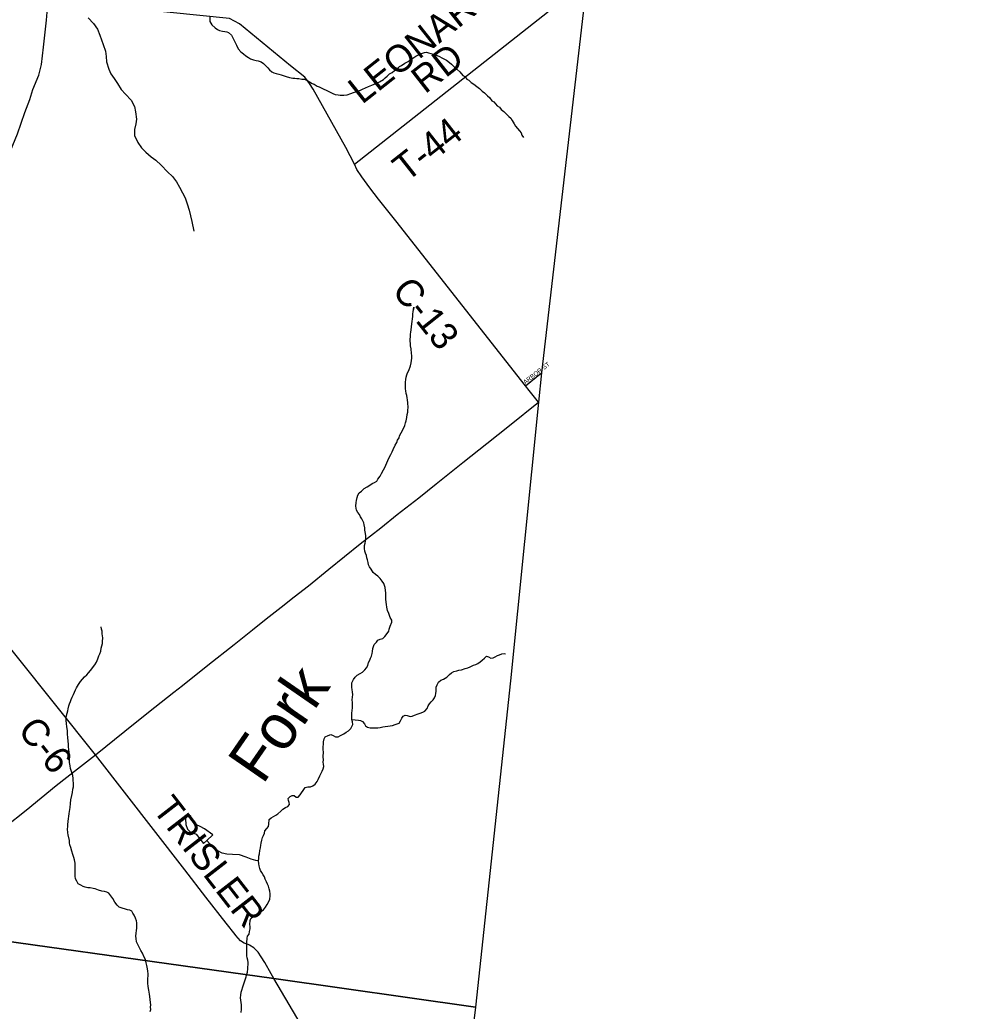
# Model space of a CAD drawing. Extents: x 1310247 to 1664935, y 235267 to 584339.
# Drawn here: x 1525713 to 1536205, y 325986 to 336990 of the extents above; entities that cross this region are included whole.
import ezdxf

# ---------------------------------------------------------------- set-up
doc = ezdxf.new("R2010")
doc.units = 0
for name, color, linetype in [('GM_X_Adjacent_County', 7, 'Continuous'), ('GM_X_County', 7, 'Continuous'), ('GM_X_County_Road', 7, 'Continuous'), ('GM_X_County_Road_Text', 7, 'Continuous'), ('GM_X_Minor_Lake', 7, 'Continuous'), ('GM_X_Minor_River', 7, 'Continuous'), ('GM_X_Minor_River_Text', 7, 'Continuous'), ('GM_X_State_Route', 7, 'Continuous'), ('GM_X_Township', 7, 'Continuous'), ('GM_X_Township_Road', 7, 'Continuous'), ('GM_X_Township_Road_Text', 7, 'Continuous'), ('GM_X_Township_Subdivision', 7, 'Continuous'), ('GM_X_Township_Subdivision_Text', 7, 'Continuous')]:
    doc.layers.add(name, color=color, linetype=linetype)

msp = doc.modelspace()

# ---------------------------------------------------------------- linework, layer by layer
at = {"layer": 'GM_X_Adjacent_County'}
msp.add_lwpolyline([(1536205, 372785), (1535397, 366216), (1534972, 363186), (1534842, 361983), (1534628, 360199), (1533821, 353172), (1533276, 348457), (1532824, 344490), (1532312, 340083), (1532006, 337422), (1531505, 333071), (1531469, 332747), (1531158, 329654), (1530772, 326029), (1530509, 323916), (1530186, 322432), (1530006, 319686), (1529806, 317987)], dxfattribs=at)
at = {"layer": 'GM_X_County'}
msp.add_lwpolyline([(1536205, 372785), (1535397, 366216), (1534972, 363186), (1534842, 361983), (1534628, 360199), (1533821, 353172), (1533276, 348457), (1532824, 344490), (1532312, 340083), (1532006, 337422), (1531505, 333071), (1531469, 332747), (1531158, 329654), (1530772, 326029), (1530509, 323916), (1530186, 322432), (1530006, 319686), (1529806, 317987)], dxfattribs=at)
at = {"layer": 'GM_X_County_Road'}
for points in [[(1526553, 328831), (1524772, 331056), (1524725, 331125), (1524709, 331149), (1524687, 331191), (1524676, 331227), (1524669, 331304), (1524684, 331466), (1524975, 333549), (1525003, 333751), (1525037, 334030), (1525046, 334096), (1525054, 334172), (1525089, 334279), (1525138, 334396), (1525688, 335724), (1525769, 335962), (1525824, 336105), (1525859, 336217), (1525923, 336377), (1525954, 336496), (1525977, 336688), (1526010, 336987), (1526027, 337210)], [(1531469, 332747), (1531366, 332875), (1531324, 332929), (1529885, 334759), (1529693, 334999), (1529599, 335124), (1529508, 335247), (1529454, 335330), (1529429, 335389), (1529333, 335574), (1528970, 336221), (1528927, 336285), (1528876, 336353), (1528719, 336480), (1528150, 336944), (1528040, 337005), (1526027, 337210)]]:
    msp.add_lwpolyline(points, dxfattribs=at)
at = {"layer": 'GM_X_Minor_Lake'}
for points in [[(1527788, 327882), (1527855, 327943), (1527764, 328011), (1527716, 328036), (1527676, 328053), (1527649, 328077), (1527623, 328118), (1527610, 328148), (1527586, 328169), (1527558, 328163), (1527553, 328121), (1527554, 328059), (1527573, 328006), (1527611, 327971), (1527643, 327961), (1527671, 327950)], [(1527671, 327950), (1527751, 327846), (1527788, 327882)]]:
    msp.add_lwpolyline(points, dxfattribs=at)
at = {"layer": 'GM_X_Minor_River'}
for points in [[(1526470, 337013), (1526531, 336948), (1526574, 336887), (1526601, 336820), (1526620, 336767), (1526637, 336715), (1526664, 336642), (1526671, 336584), (1526676, 336523), (1526703, 336441), (1526724, 336390), (1526759, 336339), (1526798, 336282), (1526838, 336218), (1526887, 336165), (1526950, 336099), (1526985, 336028), (1526998, 335968), (1527007, 335889), (1527000, 335837), (1526987, 335773), (1526985, 335707), (1527022, 335628), (1527063, 335571), (1527111, 335520), (1527170, 335471), (1527222, 335432), (1527281, 335377), (1527352, 335303), (1527409, 335250), (1527452, 335193), (1527487, 335132), (1527519, 335070), (1527550, 335013), (1527571, 334948), (1527592, 334876), (1527609, 334815), (1527624, 334751), (1527646, 334646)], [(1527823, 337024), (1527822, 336970), (1527845, 336934), (1527880, 336903), (1527906, 336884), (1527930, 336872), (1527964, 336863), (1527988, 336860), (1528010, 336856), (1528031, 336850), (1528061, 336819), (1528072, 336797), (1528090, 336768), (1528099, 336746), (1528117, 336707), (1528138, 336667), (1528167, 336634), (1528197, 336611), (1528222, 336591), (1528250, 336572), (1528275, 336556), (1528305, 336547), (1528337, 336538), (1528359, 336534), (1528391, 336523), (1528416, 336507), (1528467, 336457), (1528485, 336435), (1528511, 336412), (1528532, 336402), (1528558, 336395), (1528588, 336387), (1528614, 336380), (1528646, 336367), (1528670, 336361), (1528707, 336350), (1528743, 336343), (1528765, 336343), (1528787, 336338), (1528809, 336338), (1528845, 336333), (1528869, 336331), (1528905, 336316), (1528928, 336301), (1528958, 336285), (1528980, 336276), (1529014, 336255), (1529035, 336247), (1529079, 336224), (1529119, 336205), (1529156, 336186), (1529188, 336172), (1529214, 336163), (1529248, 336156), (1529270, 336154), (1529308, 336153), (1529348, 336158), (1529386, 336171), (1529418, 336183)], [(1529418, 336183), (1529455, 336194), (1529495, 336211), (1529517, 336221), (1529549, 336234), (1529582, 336250), (1529620, 336265), (1529665, 336282), (1529705, 336301), (1529750, 336326), (1529768, 336348), (1529790, 336366), (1529815, 336389), (1529845, 336405), (1529870, 336426), (1529902, 336447), (1529929, 336473), (1529951, 336483), (1529986, 336508), (1530022, 336529), (1530052, 336549), (1530075, 336566), (1530107, 336586), (1530129, 336597), (1530154, 336611), (1530182, 336620), (1530206, 336628), (1530228, 336631), (1530296, 336610), (1530318, 336603), (1530344, 336593), (1530371, 336582), (1530397, 336570), (1530421, 336557), (1530447, 336542), (1530482, 336516), (1530506, 336497), (1530539, 336466), (1530563, 336444), (1530598, 336413), (1530631, 336372), (1530653, 336360), (1530676, 336333), (1530698, 336321), (1530722, 336296), (1530753, 336275), (1530785, 336249), (1530816, 336226), (1530844, 336199), (1530871, 336181), (1530903, 336148), (1530926, 336129), (1530953, 336091), (1530975, 336078), (1531012, 336035), (1531038, 336019), (1531057, 335996), (1531087, 335972), (1531110, 335945), (1531140, 335918), (1531163, 335898), (1531177, 335871), (1531198, 335837), (1531216, 335808), (1531237, 335782), (1531259, 335759), (1531276, 335735), (1531286, 335711), (1531303, 335684)], [(1530075, 333726), (1530079, 333750), (1530082, 333776), (1530087, 333802), (1530084, 333776)], [(1529636, 330857), (1529611, 330892), (1529594, 330918), (1529584, 330940), (1529579, 330968), (1529573, 330995), (1529566, 331019), (1529560, 331043), (1529551, 331069), (1529541, 331094), (1529540, 331122), (1529540, 331154), (1529545, 331180), (1529549, 331204), (1529552, 331228), (1529553, 331264), (1529549, 331290), (1529544, 331324), (1529541, 331350), (1529535, 331383), (1529530, 331405), (1529520, 331429), (1529509, 331451), (1529495, 331474), (1529482, 331500), (1529464, 331522), (1529449, 331547), (1529445, 331571), (1529444, 331593), (1529446, 331631), (1529451, 331653), (1529458, 331689), (1529466, 331713), (1529479, 331739), (1529505, 331760), (1529536, 331788), (1529570, 331805), (1529599, 331825), (1529623, 331842), (1529651, 331856), (1529674, 331871), (1529688, 331893), (1529711, 331923), (1529729, 331956), (1529750, 331994), (1529765, 332022), (1529797, 332099), (1529809, 332125), (1529830, 332165), (1529845, 332195), (1529857, 332220), (1529880, 332270), (1529897, 332300), (1529905, 332324), (1529922, 332349), (1529928, 332371), (1529947, 332405), (1529964, 332439), (1529985, 332486), (1529995, 332516), (1530002, 332540), (1530009, 332576), (1530013, 332608), (1530020, 332634), (1530020, 332656), (1530023, 332688), (1530020, 332740), (1530017, 332771), (1530013, 332793), (1530008, 332819), (1530002, 332843), (1529999, 332873), (1529995, 332895), (1529994, 332918), (1529995, 332970), (1529998, 332996), (1530002, 333022), (1530009, 333048), (1530017, 333071), (1530030, 333099), (1530051, 333151), (1530055, 333181), (1530060, 333207), (1530065, 333235), (1530065, 333263), (1530062, 333287), (1530055, 333339), (1530051, 333370), (1530050, 333398), (1530047, 333424), (1530047, 333446), (1530050, 333470), (1530050, 333500), (1530053, 333522), (1530055, 333548), (1530060, 333582), (1530065, 333614), (1530067, 333642), (1530070, 333670), (1530074, 333698), (1530075, 333726)], [(1528824, 328387), (1528840, 328410), (1528857, 328436), (1528881, 328468), (1528908, 328475), (1528940, 328478), (1528966, 328486), (1528992, 328505), (1529013, 328537), (1529023, 328559), (1529042, 328597), (1529059, 328628), (1529069, 328650), (1529080, 328676), (1529089, 328702), (1529083, 328728), (1529080, 328750), (1529082, 328778), (1529081, 328810), (1529082, 328865), (1529080, 328887), (1529079, 328919), (1529082, 328951), (1529082, 328975), (1529091, 329009), (1529101, 329031), (1529136, 329048), (1529166, 329057), (1529192, 329047), (1529218, 329030), (1529246, 329032), (1529272, 329045), (1529310, 329066), (1529337, 329082), (1529361, 329097), (1529388, 329123), (1529400, 329147), (1529411, 329169), (1529405, 329197), (1529400, 329223), (1529398, 329245), (1529397, 329269), (1529397, 329291), (1529402, 329329), (1529406, 329351), (1529407, 329389), (1529404, 329414), (1529402, 329442), (1529407, 329472), (1529410, 329500), (1529406, 329526), (1529401, 329556), (1529399, 329580), (1529400, 329630), (1529417, 329666), (1529434, 329694), (1529456, 329715), (1529491, 329735), (1529517, 329750), (1529541, 329776), (1529560, 329797), (1529574, 329823), (1529585, 329857), (1529598, 329883), (1529606, 329905), (1529617, 329927), (1529625, 329957), (1529628, 329979), (1529632, 330011), (1529639, 330034), (1529647, 330058), (1529672, 330084), (1529688, 330106), (1529713, 330115), (1529741, 330123), (1529763, 330146), (1529790, 330180), (1529807, 330203), (1529811, 330227), (1529824, 330259), (1529843, 330303), (1529843, 330325), (1529824, 330356), (1529816, 330380), (1529807, 330402), (1529795, 330434), (1529788, 330469), (1529783, 330499), (1529779, 330527), (1529774, 330559), (1529775, 330607), (1529774, 330629), (1529770, 330654), (1529767, 330688), (1529761, 330710), (1529754, 330734), (1529734, 330761), (1529713, 330789), (1529687, 330814), (1529662, 330834), (1529636, 330857)], [(1526252, 328948), (1526246, 329024), (1526244, 329061), (1526241, 329101), (1526236, 329143), (1526233, 329181), (1526229, 329211), (1526228, 329241), (1526233, 329269), (1526246, 329319), (1526250, 329341), (1526257, 329377), (1526265, 329399), (1526274, 329425), (1526282, 329447), (1526295, 329473), (1526308, 329502), (1526320, 329528), (1526333, 329552), (1526343, 329574), (1526364, 329612), (1526387, 329645), (1526409, 329673), (1526430, 329697), (1526456, 329720), (1526477, 329742), (1526499, 329767), (1526545, 329832), (1526563, 329862), (1526578, 329896), (1526591, 329932), (1526601, 329954), (1526614, 329984), (1526617, 330014), (1526625, 330041), (1526630, 330069), (1526632, 330091), (1526633, 330130), (1526632, 330154), (1526628, 330176), (1526627, 330206), (1526621, 330228), (1526616, 330252)], [(1529400, 329223), (1529472, 329216), (1529494, 329211), (1529517, 329201), (1529537, 329176), (1529550, 329154), (1529572, 329139), (1529600, 329133), (1529658, 329131), (1529686, 329133), (1529714, 329136), (1529742, 329142), (1529768, 329145), (1529796, 329151), (1529825, 329154), (1529851, 329159), (1529879, 329169), (1529901, 329174), (1529923, 329184), (1529940, 329208), (1529952, 329238), (1529969, 329261), (1529991, 329271), (1530013, 329270), (1530047, 329258), (1530069, 329259), (1530095, 329271), (1530136, 329288), (1530158, 329293), (1530188, 329305), (1530210, 329316), (1530233, 329346), (1530247, 329374), (1530262, 329396), (1530280, 329421), (1530301, 329443), (1530317, 329465), (1530326, 329489), (1530330, 329511), (1530335, 329537), (1530336, 329581), (1530344, 329607), (1530361, 329638), (1530386, 329660), (1530414, 329673), (1530452, 329695), (1530481, 329722), (1530503, 329742), (1530532, 329755), (1530562, 329764), (1530584, 329772), (1530614, 329775), (1530656, 329789), (1530685, 329798), (1530713, 329809), (1530749, 329827), (1530776, 329836), (1530798, 329846), (1530822, 329863), (1530846, 329881), (1530871, 329906), (1530893, 329926), (1530915, 329920), (1530941, 329905), (1530967, 329908), (1530989, 329918), (1531014, 329934), (1531038, 329941), (1531062, 329953), (1531088, 329956), (1531103, 329953)], [(1527152, 326175), (1527145, 326219), (1527138, 326260), (1527135, 326298), (1527133, 326320), (1527134, 326348), (1527136, 326380), (1527137, 326402), (1527135, 326430), (1527132, 326458), (1527123, 326495), (1527117, 326523), (1527108, 326561), (1527095, 326587), (1527074, 326632), (1527058, 326658), (1527039, 326697), (1527022, 326725), (1527010, 326756), (1527003, 326794), (1527000, 326818), (1527004, 326854), (1527007, 326882), (1527011, 326908), (1527012, 326934), (1527011, 326968), (1527007, 326990), (1526998, 327019), (1526984, 327051), (1526969, 327075), (1526957, 327098), (1526934, 327108), (1526910, 327111), (1526886, 327119), (1526848, 327128), (1526816, 327141), (1526793, 327163), (1526767, 327198), (1526744, 327237), (1526725, 327267), (1526701, 327296), (1526678, 327306), (1526654, 327313), (1526624, 327319), (1526586, 327330), (1526550, 327343), (1526526, 327348), (1526493, 327354), (1526469, 327357), (1526439, 327363), (1526417, 327370), (1526391, 327384), (1526361, 327401), (1526346, 327428), (1526333, 327454), (1526327, 327484), (1526328, 327546), (1526327, 327580), (1526328, 327608), (1526326, 327631), (1526321, 327665), (1526314, 327693), (1526300, 327727), (1526289, 327762), (1526278, 327802), (1526270, 327832), (1526265, 327855), (1526263, 327879), (1526249, 327943), (1526247, 327967), (1526244, 328009), (1526245, 328033), (1526247, 328060), (1526250, 328092), (1526255, 328124), (1526257, 328146), (1526262, 328180), (1526269, 328226), (1526271, 328248), (1526274, 328290), (1526279, 328334), (1526290, 328382), (1526299, 328415), (1526303, 328449), (1526308, 328477), (1526309, 328516), (1526307, 328546), (1526304, 328570), (1526301, 328604), (1526293, 328626), (1526288, 328648), (1526276, 328679), (1526271, 328709), (1526266, 328747), (1526264, 328769), (1526265, 328791), (1526261, 328825), (1526260, 328858), (1526257, 328892), (1526255, 328922), (1526252, 328948)], [(1528170, 325971), (1528175, 326009), (1528174, 326035), (1528172, 326057), (1528169, 326081), (1528165, 326108), (1528162, 326136), (1528165, 326164), (1528171, 326196), (1528178, 326218), (1528189, 326258), (1528195, 326279), (1528206, 326311), (1528214, 326333), (1528227, 326369), (1528233, 326397), (1528240, 326421), (1528243, 326455), (1528245, 326477), (1528248, 326501), (1528248, 326527), (1528245, 326551), (1528237, 326577), (1528234, 326602), (1528231, 326644), (1528233, 326750), (1528236, 326796), (1528240, 326820), (1528259, 326842), (1528262, 326872), (1528268, 326900), (1528269, 326926), (1528265, 326950), (1528270, 326994), (1528277, 327016), (1528307, 327041), (1528335, 327059), (1528358, 327072), (1528390, 327092), (1528417, 327113), (1528439, 327139), (1528460, 327171), (1528475, 327198), (1528487, 327230), (1528492, 327266), (1528490, 327290), (1528487, 327320), (1528482, 327343), (1528472, 327375), (1528463, 327397), (1528451, 327422), (1528438, 327452), (1528430, 327476), (1528415, 327498), (1528401, 327527), (1528386, 327549), (1528378, 327571), (1528369, 327600), (1528365, 327622), (1528364, 327654), (1528367, 327680), (1528367, 327706), (1528372, 327734), (1528378, 327770), (1528385, 327800), (1528390, 327830), (1528392, 327852), (1528399, 327886), (1528406, 327914), (1528416, 327936), (1528429, 327964), (1528433, 327988), (1528454, 328013), (1528472, 328037), (1528477, 328063), (1528482, 328115), (1528504, 328133), (1528529, 328148), (1528553, 328162), (1528577, 328177), (1528612, 328206), (1528634, 328228), (1528663, 328246), (1528687, 328257), (1528705, 328279), (1528704, 328301), (1528696, 328323), (1528693, 328347), (1528713, 328369), (1528736, 328380), (1528760, 328382), (1528781, 328361), (1528803, 328361), (1528824, 328387)], [(1528364, 327654), (1528332, 327660), (1528280, 327673), (1528226, 327696), (1528152, 327721), (1528074, 327725), (1528012, 327730), (1527960, 327741), (1527902, 327768), (1527845, 327819), (1527788, 327882)], [(1527160, 325984), (1527167, 326006), (1527165, 326030), (1527166, 326056), (1527162, 326084), (1527161, 326115), (1527158, 326151), (1527152, 326175)]]:
    msp.add_lwpolyline(points, dxfattribs=at)
at = {"layer": 'GM_X_State_Route'}
msp.add_lwpolyline([(1525552, 328034), (1525784, 328219), (1526115, 328490), (1526355, 328676), (1526553, 328831), (1526877, 329094), (1527142, 329305), (1527424, 329528), (1527519, 329603), (1527801, 329828), (1528091, 330057), (1528295, 330218), (1528449, 330343), (1528613, 330469), (1528760, 330587), (1528919, 330709), (1529143, 330891), (1529491, 331172), (1529720, 331351), (1529902, 331499), (1530142, 331685), (1530334, 331839), (1530631, 332076), (1530898, 332288), (1531149, 332488), (1531469, 332747)], dxfattribs=at)
at = {"layer": 'GM_X_Township'}
for points in [[(1533276, 348457), (1532824, 344490), (1532312, 340083), (1532006, 337422), (1531505, 333071), (1531469, 332747), (1531158, 329654), (1530772, 326029), (1528532, 326348), (1524346, 326932), (1524319, 326936), (1516670, 327973), (1515410, 328144), (1515396, 328155), (1510688, 331967), (1508770, 333520), (1507334, 334683), (1504210, 337249), (1502439, 338703), (1501850, 339181), (1500490, 340284), (1499584, 342445), (1499395, 345650), (1499188, 348671)], [(1503185, 317642), (1504578, 323300), (1504587, 323349), (1504598, 323405), (1504652, 323631), (1505134, 325645), (1506297, 330423), (1507086, 333664), (1507334, 334683), (1508770, 333520), (1510688, 331967), (1515396, 328155), (1515410, 328144), (1516670, 327973), (1524319, 326936), (1524346, 326932), (1528532, 326348), (1530772, 326029), (1530509, 323916), (1530186, 322432), (1530006, 319686), (1529806, 317987)]]:
    msp.add_lwpolyline(points, dxfattribs=at)
at = {"layer": 'GM_X_Township_Road'}
for points in [[(1529429, 335389), (1532006, 337422)], [(1527544, 327554), (1526553, 328831)], [(1528103, 326836), (1528002, 326963), (1527777, 327253), (1527544, 327554)], [(1528262, 326718), (1528248, 326726), (1528204, 326742), (1528163, 326767), (1528111, 326825), (1528103, 326836)], [(1528502, 326402), (1528431, 326527), (1528393, 326590), (1528358, 326642), (1528341, 326660), (1528312, 326691), (1528262, 326718)], [(1530509, 323916), (1530254, 324184), (1530217, 324228), (1530173, 324241), (1530124, 324221), (1530056, 324160), (1529963, 324083), (1529910, 324061), (1529883, 324067), (1529849, 324108), (1529772, 324243), (1529555, 324618), (1528532, 326348), (1528502, 326402)]]:
    msp.add_lwpolyline(points, dxfattribs=at)
at = {"layer": 'GM_X_Township_Subdivision'}
msp.add_lwpolyline([(1531324, 332929), (1531505, 333071)], dxfattribs=at)

# ---------------------------------------------------------------- texts
at = {"layer": 'GM_X_County_Road_Text'}
for s, rotation, p in [('C-13', 308.4457, (1529833, 333982)), ('C-6', 308.5167, (1525680, 329102))]:
    msp.add_text(s, height=300, rotation=rotation, dxfattribs=at).set_placement(p)
at = {"layer": 'GM_X_Minor_River_Text'}
msp.add_text('Fork', height=500.1, rotation=55.3452, dxfattribs=at).set_placement((1528409, 328491))
at = {"layer": 'GM_X_Township_Road_Text'}
for s, rotation, p in [('LEONARD', 38.3674, (1529511, 336045)), ('RD', 37.9626, (1530210, 336161)), ('T-44', 38.2168, (1530005, 335182)), ('TRISLER', 307.8153, (1527176, 328227))]:
    msp.add_text(s, height=300, rotation=rotation, dxfattribs=at).set_placement(p)
at = {"layer": 'GM_X_Township_Subdivision_Text'}
msp.add_text('ARBOR ST', height=50, rotation=37.7245, dxfattribs=at).set_placement((1531323, 332941))

doc.saveas('drawing.dxf')
